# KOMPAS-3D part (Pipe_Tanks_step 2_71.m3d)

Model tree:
1. X Axis
2. Y Axis
3. Z Axis  (labels: Bend 90 Dn 50; Pipe Dn 50; T-Bend Dn 50)
     Òîëùèíà ñòåíêè 1 = 1

Referenced files in C:\Documents and Settings\kashirsky\Мои документы\Camtasia Studio\Pipelines3D\Tanks\: Tanks_step 2.a3d
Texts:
  Pipe Dn 50
  Steel ASTM A295
  Three Point Plane
  Plane at Angle
  Line and Point Plane
  Axis through Two Vertices
  Axis of Feature
  Axis of Conical Surface
  Axis through Edge
  Trim by Surface
  Trim by Sketch
  Feature with No History
  Intersection Axis of Two Planes
  Two Line Plane
  Line and Face Plane
  Bend by line
  Hole in sheet body
  Cut in sheet body
  Point in CM
  Linear Dimension from Line to Point
  Surface Finish Symbol
  Geometric Tolerance Symbol
  Leader #1
  Leader #2
  Leader #3
  Shape Deviations and Datum
  Node point number
  Mark of coordination axis
  Node point designation
  Mark/Reference designation with leader
  Mark/reference designation on line
  Mark/Reference designation without leader
  Bend 90 Dn 50
  T-Bend Dn 50
  Plane of section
